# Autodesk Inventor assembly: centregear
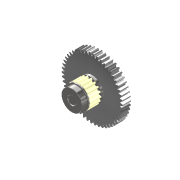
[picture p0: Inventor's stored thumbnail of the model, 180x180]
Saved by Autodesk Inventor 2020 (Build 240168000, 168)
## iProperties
Created: 2021-01
Part Number: centregear
Document SubType Name: Assembly
Designer: Greg
Author: Greg
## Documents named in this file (6)
- D:\Users\Greg\Documents\GrabCAD\2020CAD\centregear.iam
- D:\Users\Greg\Documents\GrabCAD\2020CAD\18t gear spacer.ipt
- D:\Users\Greg\Documents\GrabCAD\2020CAD\FR6ZZ Bearing.ipt
- D:\Users\Greg\Documents\GrabCAD\2020CAD\Toughbox d05.ipt
- D:\Users\Greg\Documents\GrabCAD\2020CAD\Toughbox d07.ipt
- D:\Users\Greg\Documents\GrabCAD\2020CAD\18t_Aluminum_Spur_Gear_20_DP_3_8_Hex_Bore_217-3208.ipt
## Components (6 placed, 5 different names)
1. 18t gear spacer:1 — Mate:6, Mate:7, Mate:10
2. FR6ZZ Bearing:1 — Mate:1, Mate:5, Mate:11
3. Toughbox d05:1 — Mate:3, Mate:4, Mate:5, Mate:7
4. FR6ZZ Bearing:2 — Mate:2, Mate:12
5. 18t_Aluminum_Spur_Gear_20_DP_3_8_Hex_Bore_217-3208:1 — Mate:8, Mate:9, Mate:10
6. Toughbox d07:1 — Mate:1, Mate:2, Mate:3, Mate:4, Mate:6, Mate:8, Mate:9, Mate:11, Mate:12
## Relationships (12: Mate 12)
- Mate:1: FR6ZZ Bearing:1 ↔ Toughbox d07:1
- Mate:2: FR6ZZ Bearing:2 ↔ Toughbox d07:1
- Mate:3: Toughbox d05:1 ↔ Toughbox d07:1
- Mate:4: Toughbox d05:1 ↔ Toughbox d07:1
- Mate:5: FR6ZZ Bearing:1 ↔ Toughbox d05:1
- Mate:6: 18t gear spacer:1 ↔ Toughbox d07:1
- Mate:7: 18t gear spacer:1 ↔ Toughbox d05:1
- Mate:8: 18t_Aluminum_Spur_Gear_20_DP_3_8_Hex_Bore_217-3208:1 ↔ Toughbox d07:1
- Mate:9: 18t_Aluminum_Spur_Gear_20_DP_3_8_Hex_Bore_217-3208:1 ↔ Toughbox d07:1
- Mate:10: 18t gear spacer:1 ↔ 18t_Aluminum_Spur_Gear_20_DP_3_8_Hex_Bore_217-3208:1
- Mate:11: FR6ZZ Bearing:1 ↔ Toughbox d07:1
- Mate:12: FR6ZZ Bearing:2 ↔ Toughbox d07:1
